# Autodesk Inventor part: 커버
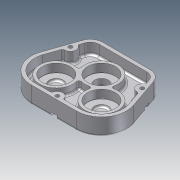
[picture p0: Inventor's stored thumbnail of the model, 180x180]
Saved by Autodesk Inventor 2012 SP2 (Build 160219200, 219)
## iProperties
Company: 한국ATC센터
Created: 2014-12
Part Number: 커버
Document SubType Name: Modeling
Designer: KYOUNG IL JANG
Density: 1 g/cm^3
Mass: 160.364 g
Surface Area: 512.085 cm^2
Volume: 160.364 cm^3
Material: 기본값
Author: KYOUNG IL JANG
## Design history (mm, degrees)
sketch "스케치1"
  geometry: L1 (-66.565, -20.803)-(-47, 36); L2 (47, 36)-(66.565, -20.803); L3 (-32.527, -68.527)-(32.527, -68.527); L4 (-47, 36)-(47, 36); C1 r 28 at (0, 0); C2 r 18 at (-32.527, -32.527); C3 r 18 at (32.527, -32.527); A1 r 36 centre (-32.527, -32.527) between (-66.565, -20.803) and (-32.527, -68.527); A2 r 36 centre (32.527, -32.527) between (32.527, -68.527) and (66.565, -20.803); 2 further points
  constraints: 8 end point, 6 tangent, 5 centre point, 4 point on circle, 3 coincident, 2 equal radius, 1 equal length, 1 horizontal alignment, 1 midpoint, 1 vertical alignment
  dimensions: "d0" = 56 diameter of C1; "d1" = 36 diameter of C2; "d2" = 90 deg dimension on point (0, 0) C3.centre C2.centre; "d3" = 36 radius of A1; "d4" = 104.52691 distance between parallel lines of L3 L4 (derived); "d5" = 94 distance of L1.end L2.start; "d65" = 36 distance from line of point (0, 0) L4
extrude "돌출1" new body sketch "스케치1" distance "d6" = 25; taper "d7" = 0 deg
fillet "모깎기1" dims "d8" = 18
feature "쉘1" dims "d9" = 9, "d10" = 5
sketch "스케치2"
  geometry: C1 r 24 at (1.635, -63.527); C2 r 24 at (66.689, -63.527); C3 r 24 at (34.162, -31); 4 further points
  constraints: 4 coincident, 3 centre point, 1 equal radius
  dimensions: "d11" = 48 diameter of C3; "d12" = 48 diameter of C2
extrude "돌출2" join sketch "스케치2" distance "d13" = 11; taper "d14" = 0 deg
hole "구멍1" diameter "d17" = 20; stored, may be unused: countersink angle "d21" = 90 deg, drill point angle "d23" = 0 deg; dims "d15" = 10, "d16" = 10, "d18" = 6, "d19" = 40, "d20" = 12, "d22" = 3
hole "구멍2" diameter "d26" = 20; stored, may be unused: countersink angle "d30" = 90 deg, drill point angle "d32" = 0 deg; dims "d24" = 10, "d25" = 10, "d27" = 6, "d28" = 40, "d29" = 12, "d31" = 3
hole "구멍3" diameter "d35" = 20; stored, may be unused: countersink angle "d39" = 90 deg, drill point angle "d41" = 118 deg; dims "d33" = 10, "d34" = 10, "d36" = 6, "d37" = 40, "d38" = 12, "d40" = 3
sketch "스케치3"
  geometry: C1 r 15 at (0, 0); C2 r 20 at (0, 0); 1 further point
  constraints: 2 centre point, 2 coincident
  dimensions: "d42" = 40 diameter of C2; "d43" = 30 diameter of C1
extrude "돌출3" join sketch "스케치3" distance "d44" = 8; taper "d45" = 0 deg
feature "면 기울기1" dims angle "d46" = 10 deg
fillet "모깎기2" dims "d47" = 3
fillet "모깎기3" dims "d48" = 0.3
fillet "모깎기6" dims "d66" = 0.1
sketch "스케치4"
  geometry: L1 (-61.837, -22.432)-(-46.453, 22.233) reference; L2 (46.453, 22.233)-(61.837, -22.432) reference; L3 (32.527, -63.527)-(-32.527, -63.527) reference; L4 (-34.162, 31)-(34.162, 31) reference; A1 r 8 centre (51.7, 7) between (49.095, 14.564) and (54.305, -0.564); A2 r 8 centre (-51.7, 7) between (-54.305, -0.564) and (-49.095, 14.564); A3 r 8 centre (0, -63.527) between (8, -63.527) and (-8, -63.527)
  constraints: 8 point on line, 6 point on circle, 3 centre point, 2 equal radius, 1 horizontal alignment, 1 midpoint
  dimensions: "d49" = 8 radius of A1; "d51" = 24 distance from line of A2.centre L4
extrude "돌출4" join sketch "스케치4" stored distance "d52" = 8; taper "d53" = 0 deg
fillet "모깎기4" dims "d54" = 3
sketch "스케치5"
  geometry: A1 r 8 centre (-51.7, 7) between (-52.144, -0.988) and (-47.131, 13.567) reference; A2 r 8 centre (0, -63.527) between (7.697, -61.345) and (-7.697, -61.345) reference; A3 r 8 centre (51.7, 7) between (47.131, 13.567) and (52.144, -0.988) reference; 1 further point
hole "구멍4" sketch "스케치5" at (0, -63.527), (-51.7, 7), (51.7, 7) diameter "d55" = 5.5; stored, may be unused: countersink angle "d59" = 90 deg, drill point angle "d61" = 118 deg; dims "d56" = 6, "d57" = 9.5, "d58" = 5.4, "d60" = 3
sketch "스케치6"
  geometry: L1 (-51.181, 23.862)-(-66.565, -20.803) reference; L2 (66.565, -20.803)-(51.181, 23.862) reference; L3 (-32.527, -68.527)-(32.527, -68.527) reference; L4 (-50.153, 11.491)-(-54.881, 13.119); L5 (-53.247, 2.509)-(-57.974, 4.137); L6 (50.153, 11.491)-(54.881, 13.119); L7 (53.247, 2.509)-(57.974, 4.137); L8 (4.75, -63.527)-(4.75, -68.527); L9 (-4.75, -63.527)-(-4.75, -68.527); A1 r 4.75 centre (-51.7, 7) between (-54.994, 3.578) and (-52.188, 11.725) reference; A2 r 4.75 centre (51.7, 7) between (52.188, 11.725) and (54.994, 3.578) reference; A3 r 4.75 centre (0, -63.527) between (4.308, -65.527) and (-4.308, -65.527) reference; 1 further point
  constraints: 12 end point, 6 perpendicular, 6 point on circle, 6 point on line, 6 tangent
extrude "돌출5" cut sketch "스케치6" distance "d62" = 5.4; taper "d63" = 0 deg
fillet "모깎기5" dims "d64" = 3
node "솔리드1"
